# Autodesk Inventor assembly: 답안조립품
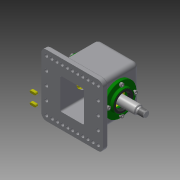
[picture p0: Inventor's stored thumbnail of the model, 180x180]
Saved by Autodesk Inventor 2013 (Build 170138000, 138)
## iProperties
Created: 2018-11
Part Number: 답안조립품
Document SubType Name: Assembly
Designer: Administrator
Author: Administrator
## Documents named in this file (8)
- C:\Users\Administrator\Desktop\481107V1017\답안조립품.iam
- C:\Users\Administrator\Desktop\481107V1017\본체.ipt
- C:\Users\Administrator\Desktop\481107V1017\커버.ipt
- C:\Users\Administrator\Desktop\481107V1017\베어링 6203.ipt
- C:\Users\Administrator\Desktop\481107V1017\축.ipt
- C:\Users\Administrator\Desktop\481107V1017\오일 실 26 38 8.ipt
- C:\Users\Administrator\Desktop\481107V1017\볼트 M4.ipt
- C:\Users\Administrator\Desktop\481107V1017\키 5x5x12.ipt
